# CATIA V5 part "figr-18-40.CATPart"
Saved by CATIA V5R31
Part number: Part1
Bounding box of the stored display mesh (mm): x -198 to 20, y -85 to 85, z 0 to 0
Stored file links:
  D:\PROJECTS\Project 2021\US EDITION\CATIA V5 6R 2021\Resources\Part Files\c18_catia_v6_6r2021_prt\figr-18-40.CATPart
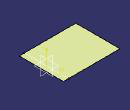
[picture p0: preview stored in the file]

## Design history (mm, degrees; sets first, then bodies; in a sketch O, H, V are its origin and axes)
Body1 (main body)
  Sketch1 on yz-plane, origin (0, 0, 0), H (0, 1, 0), V (0, 0, 1)
    line L1 (-85, 0) -> (85, 0)
    point P1 (-85, 0)
    coincidence: P1 H
    horizontal: L1 H
  Extrude1: Element1 Sketch1, Lim1 20, Lim2 198
  DatumSurface1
